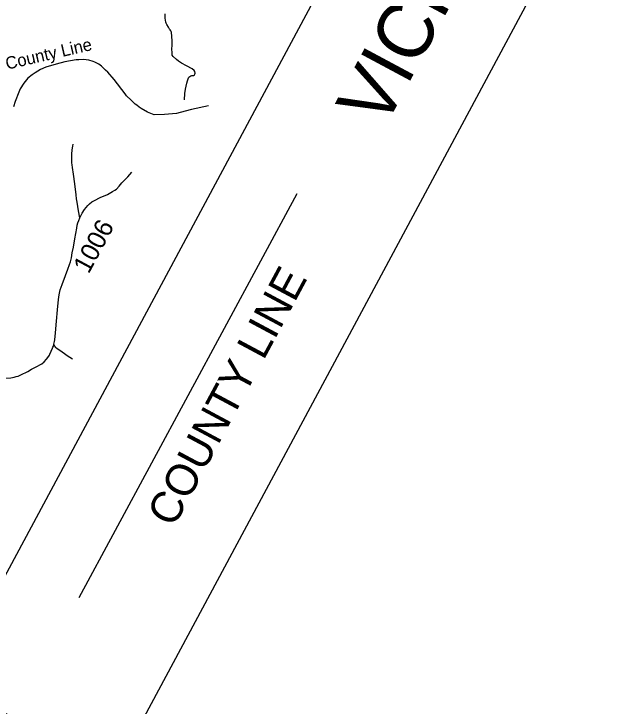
# Model space of a CAD drawing. Extents: x 1376167 to 1379209, y 761324 to 763997.
# Drawn here: x 1376637.6 to 1376772.1, y 762547.7 to 762704.2 of the extents above; entities that cross this region are included whole.
import ezdxf

# ---------------------------------------------------------------- set-up
doc = ezdxf.new("R2010")
doc.units = 0
for name, color, linetype in [('Default', 7, 'Continuous'), ('Old_Level_1', 7, 'Continuous'), ('Prop DSN Text', 7, 'Continuous'), ('Sheet Title CELL', 7, 'Continuous')]:
    doc.layers.add(name, color=color, linetype=linetype)

msp = doc.modelspace()

# ---------------------------------------------------------------- linework, layer by layer
at = {"layer": 'Default'}
msp.add_line((1376652.3, 762572.21), (1376701.57, 762663.6), dxfattribs=at)
for points in [[(1376676.1, 762684.82), (1376676.2, 762686.21), (1376676.35, 762687.16), (1376676.48, 762687.85), (1376676.68, 762688.55), (1376676.8, 762689.09), (1376676.97, 762689.56), (1376677.15, 762689.89), (1376677.53, 762690.23), (1376677.8, 762690.31), (1376678.17, 762690.31), (1376678.42, 762690.46), (1376678.47, 762690.56), (1376678.54, 762690.85), (1376678.48, 762691.16), (1376678.32, 762691.44), (1376677.86, 762691.76), (1376676.59, 762692.44), (1376675.47, 762693.09), (1376674.8, 762693.55), (1376674.33, 762693.9), (1376673.59, 762694.55), (1376673.33, 762694.91), (1376673.32, 762695.52), (1376673.31, 762696.22), (1376673.35, 762697.15), (1376673.32, 762698.13), (1376673.25, 762699.13), (1376673.18, 762700.11), (1376673.03, 762700.39), (1376672.86, 762700.64), (1376672.74, 762700.8), (1376672.51, 762701.23), (1376672.11, 762701.8), (1376671.98, 762702.12), (1376671.94, 762702.34), (1376671.77, 762703.25), (1376671.74, 762704.23)], [(1376681.54, 762683.45), (1376677.74, 762682.6), (1376675.12, 762681.94), (1376674.35, 762681.71), (1376671.64, 762681.44), (1376669.31, 762681.38), (1376667.77, 762681.98), (1376666.34, 762682.79), (1376665.86, 762683.14), (1376665.34, 762683.57), (1376665, 762683.83), (1376664.06, 762684.68), (1376663.06, 762685.7), (1376662.76, 762686.12), (1376660.22, 762689.35), (1376658.79, 762691.01), (1376658.32, 762691.5), (1376657.85, 762691.94), (1376657.38, 762692.36), (1376656.78, 762692.82), (1376656.31, 762693.11), (1376655.88, 762693.32), (1376655.5, 762693.47), (1376654.55, 762693.74), (1376653.95, 762693.83), (1376653.3, 762693.89), (1376652.24, 762693.86), (1376651.63, 762693.8), (1376649.09, 762693.36), (1376647.1, 762692.87), (1376644.81, 762692.14), (1376643.6, 762691.65), (1376642.38, 762690.91), (1376641.68, 762690.44), (1376640.71, 762689.66), (1376639.83, 762688.55), (1376639.02, 762687.28), (1376638.7, 762686.53), (1376637.86, 762684.37), (1376637.47, 762683.18)], [(1376651.62, 762663.31), (1376651.32, 762665.77), (1376651.03, 762668), (1376650.79, 762669.5), (1376650.72, 762670.1), (1376650.69, 762670.53), (1376650.64, 762671.52), (1376650.69, 762672.55), (1376650.75, 762673.37), (1376650.83, 762673.94), (1376650.88, 762674.3), (1376650.98, 762674.73)], [(1376652.5, 762658.1), (1376652.72, 762658.53), (1376653, 762659.12), (1376653.55, 762659.98), (1376653.89, 762660.41), (1376654.26, 762660.87), (1376654.69, 762661.27), (1376655.23, 762661.7), (1376655.79, 762662.05), (1376657.06, 762662.66), (1376658.7, 762663.39), (1376659.89, 762664.03), (1376660.41, 762664.36), (1376660.74, 762664.61), (1376661.34, 762665.25), (1376662.01, 762665.99), (1376663.31, 762667.38), (1376664.24, 762668.4)], [(1376652.5, 762658.1), (1376652.18, 762659.66), (1376651.89, 762661.61), (1376651.75, 762662.41), (1376651.62, 762663.31)], [(1376650.77, 762650.17), (1376651.02, 762651.44), (1376651.36, 762653.36), (1376651.79, 762655.78), (1376651.9, 762656.45), (1376652.05, 762656.96), (1376652.26, 762657.48), (1376652.5, 762658.1)], [(1376646.6, 762629.51), (1376646.74, 762630.1), (1376646.81, 762630.5), (1376646.97, 762632.1), (1376647.22, 762634.76), (1376647.46, 762637.26), (1376647.63, 762639.63), (1376647.78, 762640.68), (1376648.07, 762641.81), (1376648.46, 762642.99), (1376649.28, 762645.06), (1376649.79, 762646.49), (1376650.15, 762647.56), (1376650.34, 762648.18), (1376650.59, 762649.08), (1376650.77, 762650.17)], [(1376638.12, 762622.22), (1376638.53, 762622.33), (1376639.18, 762622.59), (1376640.7, 762623.36), (1376641.53, 762623.84), (1376642.95, 762624.59), (1376643.43, 762624.88), (1376643.86, 762625.11), (1376644.42, 762625.56), (1376644.96, 762626.17), (1376645.47, 762626.82), (1376645.6, 762627.02), (1376645.72, 762627.29), (1376646.01, 762627.92), (1376646.29, 762628.62), (1376646.39, 762628.83), (1376646.51, 762629.11), (1376646.6, 762629.51)], [(1376650.79, 762626.11), (1376649.62, 762626.88), (1376648.99, 762627.31), (1376647.95, 762628.06), (1376647.15, 762628.64), (1376647.05, 762628.78), (1376646.81, 762629.08), (1376646.6, 762629.51)], [(1376631.64, 762621.61), (1376636.87, 762621.94), (1376637.65, 762622.1), (1376638.12, 762622.22)]]:
    msp.add_lwpolyline(points, dxfattribs=at)
at = {"layer": 'Old_Level_1'}
for points in [[(1376622.61, 762553.05), (1376345.79, 762701.47), (1376550.88, 763083.99), (1376827.7, 762935.57)], [(1376345.79, 762701.47), (1376660.36, 762532.81), (1376865.45, 762915.33), (1376550.88, 763083.99)]]:
    msp.add_lwpolyline(points, close=True, dxfattribs=at)

# ---------------------------------------------------------------- texts
for s, height, rotation, p in [('VICINITY MAP', 12.5553, 61.8015, (1376721.13, 762677.89)), ('County Line', 2.7901, 13.0298, (1376636.03, 762691.59)), ('1006', 4.185, 61.8015, (1376654.47, 762645.25))]:
    msp.add_text(s, height=height, rotation=rotation, dxfattribs=at).set_placement(p)
at = {"layer": 'Prop DSN Text'}
msp.add_text('COUNTY LINE', height=7.1376, rotation=61.8015, dxfattribs=at).set_placement((1376673.68, 762587.84))
at = {"layer": 'Sheet Title CELL'}
msp.add_text('TIP PROJECT:', height=25, rotation=151.6702, dxfattribs=at).set_placement((1376704.18, 762459.13))

doc.saveas('drawing.dxf')
